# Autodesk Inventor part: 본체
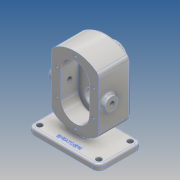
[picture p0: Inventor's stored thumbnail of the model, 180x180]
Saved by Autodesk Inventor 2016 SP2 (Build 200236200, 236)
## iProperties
Created: 2019-03
Part Number: 본체
Material: 알루미늄 6061
Document SubType Name: Modeling
Designer: EZ
Density: 2.7 g/cm^3
Appearance: 알루미늄 - 평지
Mass: 1187.19 g
Surface Area: 719.604 cm^2
Volume: 439.7 cm^3
Author: EZ
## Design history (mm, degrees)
sketch "스케치1"
  geometry: L1 (60, -36.5)-(-60, -36.5); L2 (-60, -36.5)-(-60, 36.5); L3 (-60, 36.5)-(60, 36.5); L4 (60, 36.5)-(60, -36.5); L5 (60, -36.5)-(-60, 36.5); L6 (-60, -36.5)-(60, 36.5); 1 further point
  constraints: 12 end point, 2 midpoint, 2 parallel, 1 horizontal, 1 perpendicular
  dimensions: "d0" = 120 distance of L2.end L3.end; "d1" = 73 distance of L1.end L2.end
extrude "돌출1" new body sketch "스케치1" distance "d2" = 10; taper "d3" = 0 deg
fillet "모깎기1" dims "d4" = 10
sketch "스케치2"
  geometry: L1 (-50, 36.5)-(50, 36.5) reference; L2 (60, 26.5)-(60, -26.5) reference; L3 (50, -36.5)-(-50, -36.5) reference; L4 (-60, -26.5)-(-60, 26.5) reference; A1 r 10 centre (-50, 26.5) between (-50, 36.5) and (-60, 26.5) reference; A2 r 10 centre (50, 26.5) between (60, 26.5) and (50, 36.5) reference; A3 r 10 centre (50, -26.5) between (50, -36.5) and (60, -26.5) reference; A4 r 10 centre (-50, -26.5) between (-60, -26.5) and (-50, -36.5) reference; 5 further points
  constraints: 4 coincident
hole "구멍1" sketch "스케치2" at (-50, 26.5), (-50, -26.5), (50, -26.5), (50, 26.5) diameter "d5" = 9; stored, may be unused: countersink angle "d9" = 90 deg, drill point angle "d11" = 118 deg; dims "d6" = 6, "d7" = 4, "d8" = 2, "d10" = 8
sketch "스케치3"
  geometry: L1 (36.5, 0)-(-36.5, 0) reference; L2 (-36.5, 0)-(-36.5, 10) reference; L3 (-36.5, 10)-(36.5, 10) reference; L4 (36.5, 10)-(36.5, 0) reference; L5 (-16.5, 78)-(36.5, 78); L6 (-16.5, 78)-(-16.5, 138); L7 (-16.5, 138)-(36.5, 138); L8 (36.5, 138)-(36.5, 78)
  constraints: 8 end point, 3 perpendicular, 1 horizontal
  dimensions: "d13" = 78 distance between parallel lines of L5 L1; "d14" = 138 distance between parallel lines of L1 L7; "d15" = 53 distance between parallel lines of L4 L6; "d16" = 53 distance between parallel lines of L6 L8
extrude "돌출2" join sketch "스케치3" stored distance "d18" = 80; taper "d19" = 0 deg
sketch "스케치4"
  geometry: L1 (80, 0)-(80, -120) reference; L2 (0, 0)-(80, 0) reference; L3 (0, 0)-(0, -120) reference; L4 (0, -120)-(80, -120) reference; A1 r 60 centre (40, -60) between (0, -104.721) and (80, -104.721); A2 r 60 centre (40, -60) between (80, -15.279) and (0, -15.279); A3 r 60 centre (40, -60) between (80, -104.721) and (80, -15.279); 2 further points
  constraints: 6 point on circle, 4 point on line, 3 centre point, 2 tangent, 1 midpoint, 1 vertical alignment
  dimensions: "d20" = 120 diameter of A1
extrude "돌출3" cut sketch "스케치4" distance "d21" = 80; taper "d22" = 0 deg
sketch "스케치5"
  geometry: L1 (-50, 36.5)-(50, 36.5) reference; L2 (60, 26.5)-(60, -26.5) reference; L3 (50, -36.5)-(-50, -36.5) reference; L4 (-60, -26.5)-(-60, 26.5) reference; L5 (0, 36.5)-(0, -36.5); L6 (-6, 36.5)-(-6, -6.5); L7 (-6, -6.5)-(6, -6.5); L8 (6, -6.5)-(6, 36.5); C1 r 4.5 at (50, -26.5) reference; C2 r 4.5 at (-50, 26.5) reference; C3 r 4.5 at (-50, -26.5) reference; C4 r 4.5 at (50, 26.5) reference; A1 r 10 centre (-50, 26.5) between (-50, 36.5) and (-60, 26.5) reference; A2 r 10 centre (50, 26.5) between (60, 26.5) and (50, 36.5) reference; A3 r 10 centre (50, -26.5) between (50, -36.5) and (60, -26.5) reference; A4 r 10 centre (-50, -26.5) between (-60, -26.5) and (-50, -36.5) reference
  constraints: 8 end point, 2 midpoint, 2 perpendicular, 2 point on line, 1 vertical
  dimensions: "d27" = 43 distance of L6.start L6.end; "d28" = 6 distance between parallel lines of L5 L6; "d29" = 12 distance between parallel lines of L6 L8
extrude "돌출4" join sketch "스케치5" stored distance "d30" = 80; taper "d31" = 0 deg
sketch "스케치6"
  geometry: L1 (40, 44.721)-(40, -44.721) reference; L2 (-40, 44.721)-(-40, -44.721) reference; L3 (0, 22)-(0, -22); L4 (24, 22)-(24, -22); L5 (-24, -22)-(-24, 22); A1 r 60 centre (0, 0) between (-40, -44.721) and (40, -44.721) reference; A2 r 60 centre (0, 0) between (40, 44.721) and (-40, 44.721) reference; A3 r 24 centre (0, 22) between (24, 22) and (-24, 22); A4 r 24 centre (0, -22) between (-24, -22) and (24, -22); 2 further points
  constraints: 8 end point, 4 point on circle, 4 tangent, 2 centre point, 1 midpoint, 1 parallel, 1 vertical
  dimensions: "d32" = 78 distance of point (0, -78) point (0, 0); "d34" = 22 distance of A1.centre L3.start; "d35" = 44 distance of L3.end L3.start; "d39" = 24 radius of A3
extrude "돌출5" cut sketch "스케치6" distance "d40" = 29; taper "d41" = 0 deg
sketch "스케치7"
  geometry: L1 (24, 22)-(24, -22) reference; L2 (-24, -22)-(-24, 22) reference; L3 (40, 44.721)-(40, -44.721) reference; L4 (-40, 44.721)-(-40, -44.721) reference; L5 (0, 22)-(0, -22); L6 (31, 22)-(31, -22); L7 (-31, -22)-(-31, 22); A1 r 24 centre (0, 22) between (24, 22) and (-24, 22) reference; A2 r 24 centre (0, -22) between (-24, -22) and (24, -22) reference; A3 r 60 centre (0, 0) between (-40, -44.721) and (40, -44.721) reference; A4 r 60 centre (0, 0) between (40, 44.721) and (-40, 44.721) reference; A5 r 31 centre (0, 22) between (31, 22) and (-31, 22); A6 r 31 centre (0, -22) between (-31, -22) and (31, -22); 8 further points
  constraints: 8 end point, 6 point on circle, 4 coincident, 4 tangent, 2 centre point, 1 midpoint, 1 parallel, 1 vertical
  dimensions: "d42" = 31 radius of A5
hole "구멍2" sketch "스케치7" at (0, 53), (-31, 22), (31, 22), (31, -22), (-31, -22), (0, -53) diameter "d43" = 4.134; stored, may be unused: countersink angle "d47" = 90 deg, drill point angle "d49" = 118 deg; dims "d44" = 10, "d45" = 4, "d46" = 2, "d48" = 12
sketch "스케치8"
  geometry: L1 (-33.279, 36.5)-(-33.279, -16.5) reference; L2 (-122.721, -16.5)-(-33.279, -16.5) reference; L3 (-122.721, -16.5)-(-122.721, 36.5) reference; L4 (-122.721, 36.5)-(-33.279, 36.5) reference; L5 (0, -26.5)-(0, 26.5) reference; C1 r 11 at (-78, -2.5); 1 further point
  constraints: 1 centre point
  dimensions: "d51" = 22 diameter of C1; "d52" = 78 distance from line of L5 C1.centre; "d53" = 14 distance from line of L2 C1.centre
extrude "돌출6" join sketch "스케치8" distance "d54" = 8; taper "d55" = 0 deg
hole "구멍3" diameter "d59" = 8.376; stored, may be unused: countersink angle "d63" = 90 deg, drill point angle "d65" = 118 deg; dims "d60" = 20, "d61" = 4, "d62" = 2, "d64" = 27.3, "d103" = 10, "d104" = 10
fillet "모깎기4" dims "d66" = 3
sketch "스케치10"
  geometry: L1 (-40, -44.721)-(-40, 44.721) reference; L2 (40, 44.721)-(40, -44.721) reference; L3 (6, -62.354)-(6, -65) reference; L4 (9, -68)-(60, -68) reference; L5 (60, -68)-(60, -78) reference; L6 (60, -78)-(-60, -78) reference; L7 (-60, -78)-(-60, -68) reference; L8 (-60, -68)-(-9, -68) reference; L9 (-6, -65)-(-6, -62.354) reference; L10 (-24, 22)-(-24, -22) reference; L11 (24, -22)-(24, 22) reference; C1 r 12.5 at (0, -22); A1 r 3 centre (-9, -62.354) between (-6, -62.354) and (-8.571, -59.385) reference; A2 r 60 centre (0, 0) between (-40, -44.721) and (-8.571, -59.385) reference; A3 r 60 centre (0, 0) between (40, 44.721) and (-40, 44.721) reference; A4 r 60 centre (0, 0) between (8.571, -59.385) and (40, -44.721) reference; A5 r 3 centre (9, -62.354) between (8.571, -59.385) and (6, -62.354) reference; A6 r 3 centre (9, -65) between (6, -65) and (9, -68) reference; A7 r 3 centre (-9, -65) between (-9, -68) and (-6, -65) reference; A8 r 24 centre (0, 22) between (24, 22) and (-24, 22) reference; A9 r 24 centre (0, -22) between (-24, -22) and (24, -22) reference; 1 further point
  constraints: 1 centre point, 1 coincident
  dimensions: "d72" = 25 diameter of C1
extrude "돌출7" cut sketch "스케치10" distance "d73" = 15; taper "d74" = 0 deg
sketch "스케치11"
  geometry: L1 (36.5, 122.721)-(36.5, 33.279) reference; L2 (36.5, 119)-(53.5, 119); L3 (53.5, 100)-(36.5, 100); L4 (-16.5, 56)-(-16.5, 100) reference; L5 (-16.5, 78)-(36.5, 78); L6 (-26.5, 0)-(26.5, 0) reference; L7 (53.5, 119)-(53.5, 100); 2 further points
  constraints: 8 end point, 2 horizontal, 2 midpoint, 2 point on line, 1 perpendicular, 1 vertical
  dimensions: "d76" = 78 distance between parallel lines of L6 L5; "d77" = 22 distance between parallel lines of L5 L3; "d79" = 17 distance of L2.start L2.end; "d80" = 38 diameter of L2 L3
revolve "회전1" sketch "스케치11" stored, may be unused: angle "d81" = 90 deg
fillet "모깎기6" dims "d82" = 3
sketch "스케치12"
  geometry: L1 (-16.5, 32)-(12.5, 32) reference; L2 (12.5, 32)-(12.5, 43.5) reference; L3 (12.5, 43.5)-(27.5, 43.5) reference; L4 (27.5, 43.5)-(27.5, 68.5) reference; L5 (27.5, 68.5)-(12.5, 68.5) reference; L6 (12.5, 68.5)-(12.5, 124) reference; L7 (12.5, 124)-(-16.5, 124) reference; L8 (-16.5, 124)-(-16.5, 128.933) reference; L9 (-16.5, 128.933)-(-4.5, 128.933) reference; L10 (-4.5, 128.933)-(-3.258, 131) reference; L11 (-3.258, 131)-(-4.5, 133.067) reference; L12 (-4.5, 133.067)-(-16.5, 133.067) reference; L13 (-16.5, 133.067)-(-16.5, 138) reference; L14 (-16.5, 138)-(36.5, 138) reference; L15 (36.5, 138)-(36.5, 122) reference; L16 (39.5, 119)-(53.5, 119) reference; L17 (53.5, 119)-(53.5, 81) reference; L18 (53.5, 81)-(39.5, 81) reference; L19 (36.5, 78)-(36.5, 0) reference; L20 (36.5, 0)-(-36.5, 0) reference; L21 (-36.5, 0)-(-36.5, 10) reference; L22 (-36.5, 10)-(-6.5, 10) reference; L23 (-6.5, 10)-(-6.5, 18) reference; L24 (-6.5, 18)-(-16.5, 18) reference; L25 (-16.5, 18)-(-16.5, 22.933) reference; L26 (-16.5, 22.933)-(-4.5, 22.933) reference; L27 (-4.5, 22.933)-(-3.258, 25) reference; L28 (-3.258, 25)-(-4.5, 27.067) reference; L29 (-4.5, 27.067)-(-16.5, 27.067) reference; L30 (-16.5, 27.067)-(-16.5, 32) reference; L31 (12.5, 78)-(36.5, 78); L32 (12.5, 100)-(53.5, 100); L33 (12.5, 112.5)-(27.5, 112.5); L34 (27.5, 112.5)-(27.5, 108.5); L35 (27.5, 108.5)-(46.2, 108.5); L36 (46.2, 108.5)-(46.2, 113.5); L37 (46.7, 114)-(53.5, 114); L38 (12.5, 112.5)-(12.5, 100); L39 (53.5, 114)-(53.5, 100); A1 r 3 centre (39.5, 122) between (36.5, 122) and (39.5, 119) reference; A2 r 3 centre (39.5, 78) between (39.5, 81) and (36.5, 78) reference; A3 r 0.5 centre (46.7, 113.5) between (46.7, 114) and (46.2, 113.5); 2 further points
  constraints: 18 end point, 7 point on line, 4 perpendicular, 2 collinear, 2 horizontal, 2 point on circle, 2 tangent, 1 centre point, 1 midpoint, 1 vertical
  dimensions: "d83" = 78 distance between parallel lines of L20 L31; "d84" = 22 distance between parallel lines of L31 L32; "d85" = 7.3 distance of point (46.2, 114) L37.end; "d86" = 15 distance of L33.start L33.end; "d87" = 25 diameter of L33 L32; "d88" = 17 diameter of L35 L32; "d89" = 28 diameter of L37 L32; "d90" = 0.5 radius of A3
revolve "회전2" sketch "스케치12" stored, may be unused: angle "d91" = 90 deg
fillet "모깎기7" dims "d92" = 3
fillet "모깎기8" dims "d93" = 3
fillet "모깎기9" dims "d94" = 3
fillet "모깎기10" dims "d95" = 10
chamfer "모따기1" distance "d96" = 1; stored, may be unused: second distance "d97" = 2, angle "d98" = 30 deg
sketch "스케치13"
  geometry: L1 (-50, -36.5)-(50, -36.5) reference; L2 (-60, 26.5)-(-60, -26.5) reference; 2 further points
  constraints: 1 other
  dimensions: "d99" = 10 distance from line of point (0, -26.5) L1; "d100" = 60 distance from line of L2 point (0, -26.5)
feature "엠보싱1" sketch "스케치13" dims "d0" = 120, "d1" = 73, "d101" = 0.5, "d102" = 0
chamfer "모따기2" distance "d105" = 0.7; stored, may be unused: second distance "d106" = 2, angle "d107" = 30 deg
node "솔리드1"
mirror "대칭1"
mirror "대칭2"
node "투영된 루프1"
node "투영된 루프2"
node "투영된 루프3"
node "투영된 루프4"
node "투영된 루프5"
node "투영된 루프6"
node "절단 모서리 투영1"
node "절단 모서리 투영3"
node "절단 모서리 투영4"
